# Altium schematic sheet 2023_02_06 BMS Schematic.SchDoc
size B; SheetNumber: 1; SheetTotal: 1
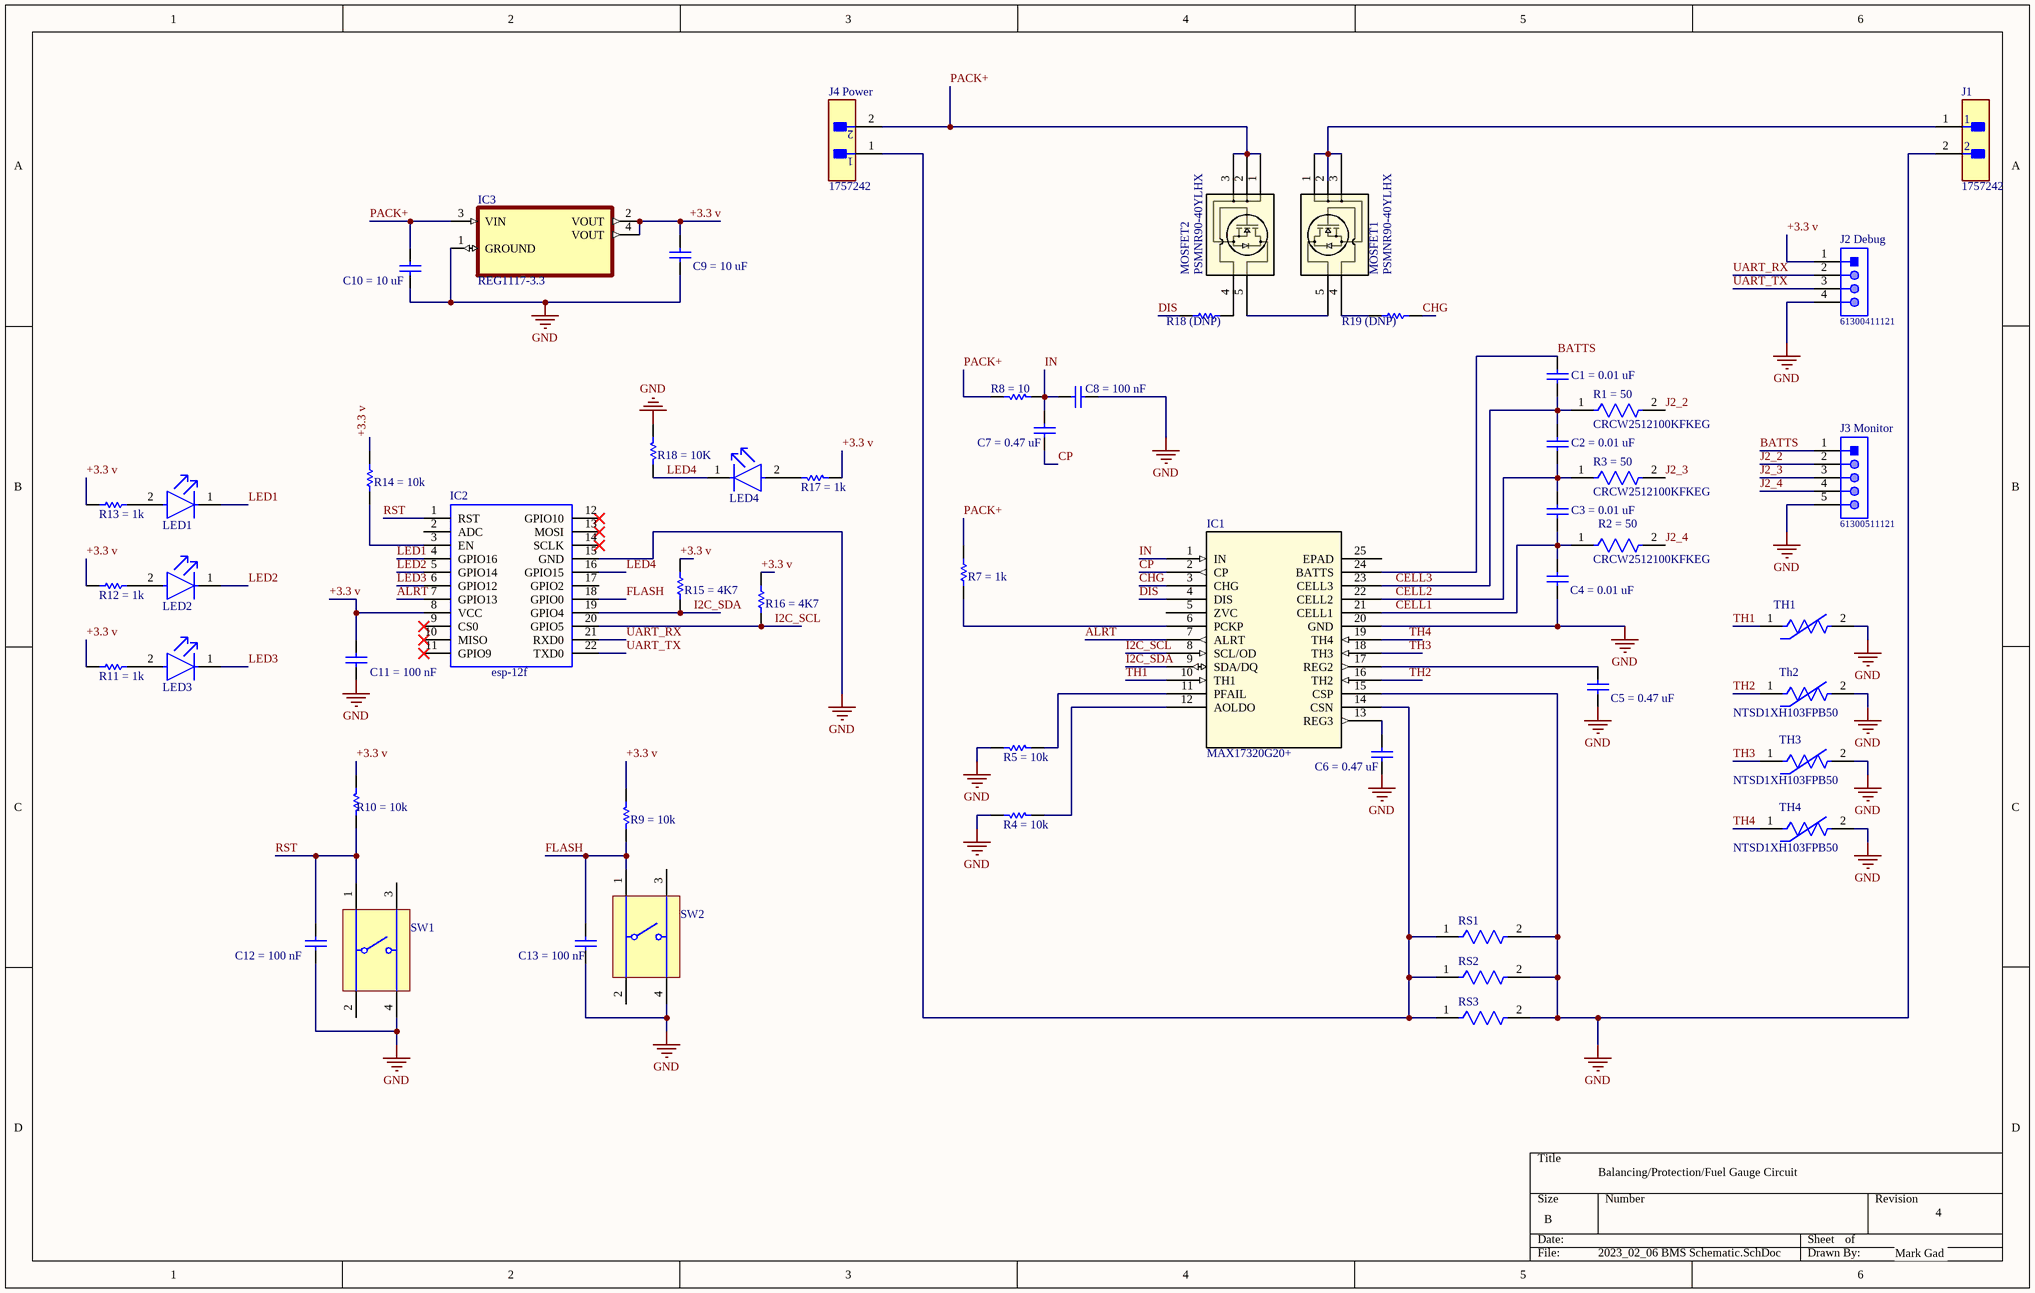
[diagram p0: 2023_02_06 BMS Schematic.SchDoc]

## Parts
C1_=_0.01_uF  CC0603JRNPO9BN101  [CAPC1608X90X40ML10T20]  (value not drawn)
C2_=_0.01_uF  CC0603JRNPO9BN101  [CAPC1608X90X40ML10T20]  (value not drawn)
C3_=_0.01_uF  CC0603JRNPO9BN101  [CAPC1608X90X40ML10T20]  (value not drawn)
C4_=_0.01_uF  CC0603JRNPO9BN101  [CAPC1608X90X40ML10T20]  (value not drawn)
C5_=_0.47_uF  CC0603JRNPO9BN101  [CAPC1608X90X40ML10T20]  (value not drawn)
C6_=_0.47_uF  CC0603JRNPO9BN101  [CAPC1608X90X40ML10T20]  (value not drawn)
C7_=_0.47_uF  CC0603JRNPO9BN101  [CAPC1608X90X40ML10T20]  (value not drawn)
C8_=_100_nF  CC0603JRNPO9BN101  [CAPC1608X90X40ML10T20]  (value not drawn)
C9_=_10_uF  CC0603JRNPO9BN101  [CAPC1608X90X40ML10T20]  (value not drawn)
C10_=_10_uF  CC0603JRNPO9BN101  [CAPC1608X90X40ML10T20]  (value not drawn)
C11_=_100_nF  CC0603JRNPO9BN101  [CAPC1608X90X40ML10T20]  (value not drawn)
C12_=_100_nF  CC0603JRNPO9BN101  [CAPC1608X90X40ML10T20]  (value not drawn)
C13_=_100_nF  CC0603JRNPO9BN101  [CAPC1608X90X40ML10T20]  (value not drawn)
IC1  MAX17320G20+  [21-0139I_T2444-4_MXM]
IC2  esp-12f  [esp12f]
IC3  REG1117-3.3  [SOT230P700X180-4N]
J1  1757242  [FP-1757242-MFG]
J2_Debug  61300411121  [61300411121]
J3_Monitor  61300511121  [61300511121]
J4_Power  1757242  [FP-1757242-MFG]
LED1  APA1606SYCK  [FP-APA1606SYCK-MFG]  (value not drawn)
LED2  APA1606SYCK  [FP-APA1606SYCK-MFG]  (value not drawn)
LED3  APA1606SYCK  [FP-APA1606SYCK-MFG]  (value not drawn)
LED4  APA1606SYCK  [FP-APA1606SYCK-MFG]  (value not drawn)
MOSFET1  PSMNR90-40YLHX  [LFPAK56E_SOT1023_NEX]
MOSFET2  PSMNR90-40YLHX  [LFPAK56E_SOT1023_NEX]
R1_=_50  CRCW2512100KFKEG  [FP-CRCW2512-e3-MFG]
R2_=_50  CRCW2512100KFKEG  [FP-CRCW2512-e3-MFG]
R3_=_50  CRCW2512100KFKEG  [FP-CRCW2512-e3-MFG]
R4_=_10k  CRCW060310K0FKEA  [RESC1609X50X30NL8T20]  (value not drawn)
R5_=_10k  CRCW060310K0FKEA  [RESC1609X50X30NL8T20]  (value not drawn)
R7_=_1k  CRCW060310K0FKEA  [RESC1609X50X30NL8T20]  (value not drawn)
R8_=_10  CRCW060310K0FKEA  [RESC1609X50X30NL8T20]  (value not drawn)
R9_=_10k  CRCW060310K0FKEA  [RESC1609X50X30NL8T20]  (value not drawn)
R10_=_10k  CRCW060310K0FKEA  [RESC1609X50X30NL8T20]  (value not drawn)
R11_=_1k  CRCW060310K0FKEA  [RESC1609X50X30NL8T20]  (value not drawn)
R12_=_1k  CRCW060310K0FKEA  [RESC1609X50X30NL8T20]  (value not drawn)
R13_=_1k  CRCW060310K0FKEA  [RESC1609X50X30NL8T20]  (value not drawn)
R14_=_10k  CRCW060310K0FKEA  [RESC1609X50X30NL8T20]  (value not drawn)
R15_=_4K7  CRCW060310K0FKEA  [RESC1609X50X30NL8T20]  (value not drawn)
R16_=_4K7  CRCW060310K0FKEA  [RESC1609X50X30NL8T20]  (value not drawn)
R17_=_1k  CRCW060310K0FKEA  [RESC1609X50X30NL8T20]  (value not drawn)
R18_(DNP)  CRCW060310K0FKEA  [RESC1609X50X30NL8T20]  (value not drawn)
R18_=_10K  CRCW060310K0FKEA  [RESC1609X50X30NL8T20]  (value not drawn)
R19_(DNP)  CRCW060310K0FKEA  [RESC1609X50X30NL8T20]  (value not drawn)
RS1  CRCW2512100KFKEG  [FP-CRCW2512-e3-MFG]  (value not drawn)
RS2  CRCW2512100KFKEG  [FP-CRCW2512-e3-MFG]  (value not drawn)
RS3  CRCW2512100KFKEG  [FP-CRCW2512-e3-MFG]  (value not drawn)
SW1  1825910-6  [TECO-1825910-6_V]  (value not drawn)
SW2  1825910-6  [TECO-1825910-6_V]  (value not drawn)
TH1  NTSD1XH103FPB50  [FP-NTSD1_FPB50-MFG]  (value not drawn)
Th2  NTSD1XH103FPB50  [FP-NTSD1_FPB50-MFG]
TH3  NTSD1XH103FPB50  [FP-NTSD1_FPB50-MFG]
TH4  NTSD1XH103FPB50  [FP-NTSD1_FPB50-MFG]

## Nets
GND: C4_=_0.01_uF.2 C5_=_0.47_uF.2 C6_=_0.47_uF.2 C8_=_100_nF.1 C9_=_10_uF.1 C10_=_10_uF.1 C11_=_100_nF.1 C12_=_100_nF.2 C13_=_100_nF.2 IC1.15(CSP) IC1.20(GND) IC2.15(GND) IC3.1(GROUND) J1.2 J2_Debug.4 J3_Monitor.5 R4_=_10k.2 R5_=_10k.2 R18_=_10K.2 RS1.2 RS2.2 RS3.2 SW1.4 SW2.4 TH1.2 Th2.2 TH3.2 TH4.2
+3.3 v: C9_=_10_uF.2 C11_=_100_nF.2 IC2.8(VCC) IC3.2(VOUT) IC3.4(VOUT) J2_Debug.1 R9_=_10k.2 R10_=_10k.1 R11_=_1k.2 R12_=_1k.2 R13_=_1k.2 R14_=_10k.2 R15_=_4K7.2 R16_=_4K7.2 R17_=_1k.2
ALRT: IC1.7(ALRT) IC2.7(GPIO13)
BATTS: C1_=_0.01_uF.1 IC1.24(BATTS) J3_Monitor.1
CELL1: C3_=_0.01_uF.2 C4_=_0.01_uF.1 IC1.21(CELL1) R2_=_50.1
CELL2: C2_=_0.01_uF.2 C3_=_0.01_uF.1 IC1.22(CELL2) R3_=_50.1
CELL3: C1_=_0.01_uF.2 C2_=_0.01_uF.1 IC1.23(CELL3) R1_=_50.1
CHG: IC1.3(CHG) R19_(DNP).1
CP: C7_=_0.47_uF.2 IC1.2(CP)
DIS: IC1.4(DIS) R18_(DNP).2
FLASH: C13_=_100_nF.1 IC2.18(GPIO0) R9_=_10k.1 SW2.1
I2C_SCL: IC1.8(SCL/OD) IC2.20(GPIO5) R16_=_4K7.1
I2C_SDA: IC1.9(SDA/DQ) IC2.19(GPIO4) R15_=_4K7.1
IN: C7_=_0.47_uF.1 C8_=_100_nF.2 IC1.1(IN) R8_=_10.2
J2_2: J3_Monitor.2 R1_=_50.2
J2_3: J3_Monitor.3 R3_=_50.2
J2_4: J3_Monitor.4 R2_=_50.2
LED1: IC2.4(GPIO16) LED1.1(C)
LED2: IC2.5(GPIO14) LED2.1(C)
LED3: IC2.6(GPIO12) LED3.1(C)
LED4: IC2.16(GPIO15) LED4.1(C) R18_=_10K.1
PACK+: C10_=_10_uF.2 IC3.3(VIN) J4_Power.2 MOSFET2.1 MOSFET2.2 MOSFET2.3 R7_=_1k.2 R8_=_10.1
RST: C12_=_100_nF.1 IC2.1(RST) R10_=_10k.2 SW1.1
TH1: IC1.10(TH1) TH1.1
TH2: IC1.16(TH2) Th2.1
TH3: IC1.18(TH3) TH3.1
TH4: IC1.19(TH4) TH4.1
UART_RX: IC2.21(RXD0) J2_Debug.2
UART_TX: IC2.22(TXD0) J2_Debug.3
NetC5_=_0.47_uF_1: C5_=_0.47_uF.1 IC1.17(REG2)
NetC6_=_0.47_uF_1: C6_=_0.47_uF.1 IC1.13(REG3)
NetIC1_6: IC1.6(PCKP) R7_=_1k.1
NetIC1_11: IC1.11(PFAIL) R5_=_10k.1
NetIC1_12: IC1.12(AOLDO) R4_=_10k.1
NetIC1_14: IC1.14(CSN) J4_Power.1 RS1.1 RS2.1 RS3.1
NetIC2_3: IC2.3(EN) R14_=_10k.1
NetJ1_1: J1.1 MOSFET1.1 MOSFET1.2 MOSFET1.3
NetLED1_2: LED1.2(A) R13_=_1k.1
NetLED2_2: LED2.2(A) R12_=_1k.1
NetLED3_2: LED3.2(A) R11_=_1k.1
NetLED4_2: LED4.2(A) R17_=_1k.1
NetMOSFET1_4: MOSFET1.4 R19_(DNP).2
NetMOSFET1_5: MOSFET1.5 MOSFET2.5
NetMOSFET2_4: MOSFET2.4 R18_(DNP).1

Not connected (* = marked no-connect by the designer): IC1 5(ZVC) 25(EPAD); IC2 2(ADC) 9(CS0)* 10(MISO)* 11(GPIO9)* 12(GPIO10)* 13(MOSI)* 14(SCLK)* 17(GPIO2); SW1 2 3; SW2 2 3

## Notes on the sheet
- Balancing/Protection/Fuel Gauge Circuit
- 4
- Mark Gad

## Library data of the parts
C1_=_0.01_uF C2_=_0.01_uF C3_=_0.01_uF C4_=_0.01_uF C5_=_0.47_uF C6_=_0.47_uF C7_=_0.47_uF C8_=_100_nF C9_=_10_uF C10_=_10_uF C11_=_100_nF C12_=_100_nF C13_=_100_nF = CMP-2100-03594-1: Chip Capacitor, 100 pF, +/- 5%, 50 V, -55 to 125 degC, 0603 (1608 Metric), RoHS, Tape and Reel; Manufacturer: Yageo; Capacitance: 100pF; Voltage Rating (DC): 50V; Dielectric: C0G; Temperature Coefficient: 30ppm/degC; Insulation Resistance: 100GR
IC1 = MAX17320G20+: No Description Available; Mfr_Name: Maxim Integrated Products
IC2 = esp-12f: ESP-12F ESP8266 Wifi Wireless IoT Board Module , package 1 x ESP8266 Adapter Plate  1pcs; Manufacturer_Name: Ai-Thinker; Geometry.Height: 3.1mm
IC3 = REG1117-3.3: 800-mA, 15-V, linear voltage regulator 4-SOT-223 -40 to 125; MF: Texas Instruments
J1 J4_Power = CMP-09399-000010-1: TERM BLOCK HDR 2POS 90DEG 5.08MM; Number of Poles: 2; Voltage Rating (DC): 320V; Number of Levels: 1; Voltage Rating: 250V; Current: 15A; Gender: Male; Current Rating: 12A; Voltage: 300V; Approvals: UL; Connector Type: Plug
J2_Debug = CMP-1502-01064-1: THT Vertical Pin Header WR-PHD, Pitch 2.54 mm, Single Row, 4 pins; Manufacturer: Wurth Elektronik; Withstanding Voltage: 500VAC; Rated Current: 3A; Working Voltage: 250VAC; Pin Number: 4; Gender: Male; Contact Resistance: 20mOhm; Pitch: 2.54mm
J3_Monitor = CMP-1502-01068-1: THT Vertical Pin Header WR-PHD, Pitch 2.54 mm, Single Row, 5 pins; Manufacturer: Wurth Elektronik; Pin Number: 5; Contact Resistance: 20mOhm; Working Voltage: 250VAC; Pitch: 2.54mm; Withstanding Voltage: 500VAC; Rated Current: 3A; Gender: Male
LED1-LED4 = CMP-44529-000039-1: LED YELLOW CLEAR CHIP SMD R/A; Forward Current: 20mA; Luminous Intensity: 150mcd; Power Rating: 75mW; Viewing Angle: 110°; Dominant Wavelength: 590nm; Number of LEDs: 1; Forward Voltage: 2V
MOSFET1 MOSFET2 = PSMNR90-40YLHX: No Description Available; Mfr_Name: Nexperia
R1_=_50 R2_=_50 R3_=_50 RS1-RS3 = CMP-02407-004199-1: RES Thick Film, 100kΩ, 1%, 1W, 100ppm/°C, 2512; Voltage Rating: 500V; Resistance: 100kR
R4_=_10k R5_=_10k R7_=_1k R8_=_10 R9_=_10k R10_=_10k R11_=_1k R12_=_1k R13_=_1k R14_=_10k R15_=_4K7 R16_=_4K7 R17_=_1k R18_(DNP) R18_=_10K R19_(DNP) = CMP-1666-00005-4: Chip Resistor, 10 KOhm, +/- 1%, 100 mW, -55 to 155 degC, 0603 (1608 Metric), RoHS, Tape and Reel; Manufacturer: Vishay Semiconductor; Voltage Rating: 75 V
SW1 SW2 = CMP-1684-00021-1: Tact Switch, SPST-NO, 0.05 A, -35 to 85 degC, 4-Pin THD, RoHS, Bulk; Manufacturer: TE Connectivity; Maximum Contact Resistance: 100mOhm; Mechanical Life: 100000Cycles; Bushing Type: Unthreaded; Switch Configuration: OFF(ON); Maximum DC Voltage Rating: 24V; Contact Rating @ Voltage: 0.05A@24VDC; Actuator Color: Black; Body Orientation: Straight; Function: MomentaryContact; Illumination: N/R; Actuator Style: RoundButton; Actuator Material: PolybutyleneTerephthalate; Dielectric Strength: 500VAC; Pole Throw Configuration: SPST; Actuator Length: 1.4mm
TH1 Th2 TH3 TH4 = CMP-06022-000470-1: Thermistor NTC 10K Ohm 1% 2-Pin Wire 3434K; Max Power Dissipation: 15mW; Accuracy: 0.5%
